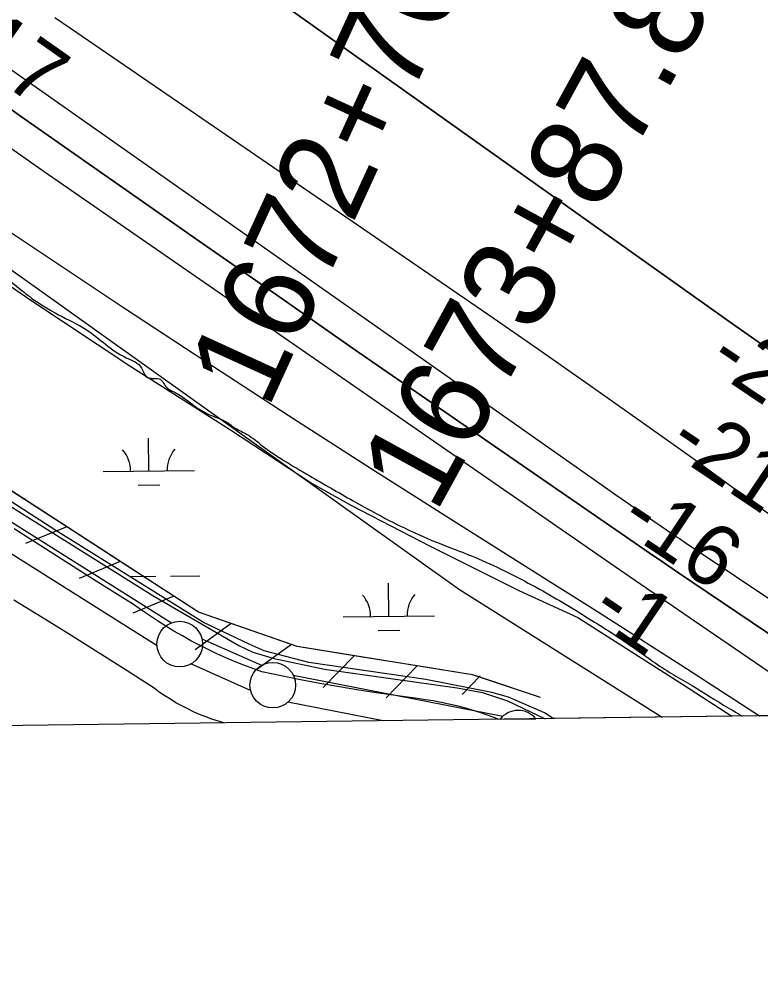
# Model space of a CAD drawing. Extents: x 3734862 to 3772949, y 391520 to 417239.
# Drawn here: x 3760790 to 3761603, y 396853 to 397909 of the extents above; entities that cross this region are included whole.
import ezdxf

# ---------------------------------------------------------------- set-up
doc = ezdxf.new("R2010")
doc.units = 0
for name, color, linetype in [('V-FLOD-BASE', 7, 'Continuous'), ('V-GRID-FRAM', 7, 'Continuous'), ('V-LEVE-TOET', 7, 'Continuous'), ('V-RIVR-EDGE', 7, 'Continuous'), ('V-RIVR-RANG', 7, 'Continuous'), ('V-RRAP-FSHR', 7, 'Continuous'), ('V-SURV-IDEN', 7, 'Continuous'), ('V-SURV-LINE', 7, 'Continuous'), ('V-TOPO-DPTH', 7, 'Continuous'), ('V-TOPO-MINR', 7, 'Continuous'), ('V-TOPO-WATR', 7, 'Continuous'), ('V-WETL-SWMP', 7, 'Continuous')]:
    doc.layers.add(name, color=color, linetype=linetype)

msp = doc.modelspace()

# ---------------------------------------------------------------- linework, layer by layer
at = {"layer": 'V-FLOD-BASE'}
for points in [[(3760932.3, 397256.2), (3760923.6, 397262.2), (3760914.9, 397268.4), (3760871.2, 397295.8), (3760827.6, 397323.3), (3760784.1, 397351)], [(3761315.1, 397142.5), (3761311.1, 397144.1), (3761302.9, 397147.1), (3761294.6, 397150), (3761286.2, 397152.6), (3761277.8, 397155), (3761269.3, 397157.2), (3761260.8, 397159.2), (3761252.2, 397161), (3761243.6, 397162.6), (3761234.9, 397164), (3761226.3, 397165.2), (3761204.8, 397168.1), (3761183.4, 397171.2), (3761162, 397174.5), (3761140.6, 397178.1), (3761119.3, 397181.9), (3761098, 397185.8), (3761076.8, 397190), (3761055.6, 397194.4), (3761045.6, 397198), (3761035.7, 397201.8), (3761025.8, 397205.8), (3761016, 397210), (3761006.3, 397214.3), (3760996.7, 397218.9), (3760987.2, 397223.7), (3760977.8, 397228.6), (3760968.5, 397233.8), (3760959.3, 397239.1), (3760950.2, 397244.6), (3760941.2, 397250.3), (3760932.3, 397256.2)]]:
    msp.add_lwpolyline(points, dxfattribs=at)
at = {"layer": 'V-GRID-FRAM'}
msp.add_lwpolyline([(3738832.3, 415033.8), (3770599.2, 415447.4), (3770843.8, 397266.6), (3739061.1, 396852.8), (3738832.3, 415033.8)], dxfattribs=at)
at = {"layer": 'V-LEVE-TOET'}
for points in [[(3759928.3, 397912.9), (3760072.5, 397820.1), (3760212, 397734.9), (3760300.9, 397673.2), (3760418.6, 397603.9), (3760544.6, 397524.6), (3760663.5, 397449.4), (3760793.1, 397367.7), (3760937.3, 397277.3), (3761030.3, 397223.2), (3761045.6, 397216.2), (3761069.1, 397209.2), (3761124.5, 397197.4), (3761269.8, 397177), (3761297.4, 397171.7), (3761325.1, 397162.9), (3761366.4, 397143.2)], [(3760814.6, 397254.1), (3760783.6, 397273.1)], [(3761014.1, 397138.6), (3761000.9, 397142.6), (3760994.1, 397145.1), (3760987.4, 397147.8), (3760980.8, 397150.7), (3760974.3, 397153.8), (3760967.8, 397157.1), (3760961.5, 397160.7), (3760955.3, 397164.4), (3760949.2, 397168.3), (3760943.2, 397172.4), (3760937.4, 397176.7), (3760906.8, 397196.3), (3760876.2, 397215.8), (3760845.4, 397235), (3760814.6, 397254.1)]]:
    msp.add_lwpolyline(points, dxfattribs=at)
at = {"layer": 'V-RIVR-EDGE'}
for points in [[(3755702.1, 404495.3), (3755757.2, 404470.8), (3755793.3, 404451.2), (3755852.5, 404424.4), (3755881.4, 404415.7), (3755906.2, 404404.4), (3755920.2, 404395.8), (3755948.7, 404379.4), (3755958.2, 404378.9), (3755969, 404378), (3755990.7, 404368.5), (3756022.8, 404350.3), (3756054.8, 404336.6), (3756079.7, 404323), (3756103.6, 404309.4), (3756144.2, 404288), (3756167.7, 404269), (3756188.9, 404253.6), (3756231.4, 404233.1), (3756271.6, 404217.2), (3756299.1, 404203.1), (3756403, 404163.5), (3756460.4, 404140.3), (3756508.7, 404114.9), (3756530.8, 404104), (3756588.2, 404078), (3756639.2, 404052.1), (3756694.3, 404019.5), (3756726.8, 403998.1), (3756735.8, 403989.1), (3756740.3, 403979.6), (3756740.3, 403973.2), (3756740.7, 403967.8), (3756747.5, 403960.5), (3756759.7, 403953.7), (3756786.3, 403941.5), (3756814.3, 403929.2), (3756864.5, 403904.6), (3756889.3, 403896), (3756899.7, 403897.3), (3756908.3, 403901.8), (3756919.2, 403901.3), (3756933.2, 403894.1), (3756945.8, 403892.7), (3756956.2, 403893.1), (3756962.1, 403897.2), (3756970.7, 403896.7), (3756978.4, 403894.4), (3756992.4, 403894.8), (3757002.8, 403897.5), (3757019.1, 403901.5), (3757027.7, 403901.5), (3757034, 403901.1), (3757036.3, 403896.5), (3757036.7, 403891.1), (3757038.5, 403883.4), (3757046.6, 403874.3), (3757060.6, 403866.2), (3757076.4, 403853.9), (3757104.4, 403831.2), (3757122.4, 403816.7), (3757145.5, 403804.5), (3757165.3, 403796.7), (3757181.6, 403787.2), (3757194.2, 403777.7), (3757213.6, 403765.4), (3757229.9, 403756.3), (3757251.6, 403745.9), (3757266.5, 403741.3), (3757283.2, 403734.5), (3757308.9, 403720.9), (3757360.4, 403694.1), (3757393.8, 403670.9), (3757430, 403657.3), (3757461.6, 403645.4), (3757505.4, 403628.1), (3757548.3, 403610.4), (3757591.7, 403587.2), (3757649.5, 403552.3), (3757711.8, 403512.8), (3757753.8, 403493.2), (3757766.9, 403487.8), (3757773.2, 403487.8), (3757785.9, 403494.1), (3757794.5, 403494), (3757803.5, 403489.5), (3757807.1, 403480.9), (3757810.6, 403456), (3757814.2, 403447.9), (3757826.4, 403437), (3757854.4, 403422.9), (3757930.3, 403373.9), (3757975.8, 403342.6), (3758005.2, 403323.5), (3758062.1, 403286.7), (3758092.3, 403263.6), (3758175.8, 403209.6), (3758234.5, 403169.2), (3758283.7, 403133.8), (3758328.8, 403103.4), (3758399.2, 403041.7), (3758421.8, 403023.1), (3758438.1, 403017.7), (3758463.8, 403017.6), (3758491.4, 403026.1), (3758504.5, 403022), (3758513.6, 403014.3), (3758514, 403006.2), (3758499.9, 402997.2), (3758498.1, 402989.9), (3758502.2, 402978.2), (3758510.7, 402969.6), (3758522, 402962.8), (3758545, 402948.7), (3758582.1, 402926.9), (3758650.2, 402878.8), (3758697.6, 402840.7), (3758721.5, 402820.3), (3758740.9, 402809.4), (3758782, 402784.9), (3758831.2, 402755.4), (3758902.1, 402711.8), (3758960.4, 402675.5), (3759018.6, 402634.6), (3759069.6, 402599.7), (3759134.6, 402553.4), (3759185.6, 402508.1), (3759223.5, 402478.1), (3759262.3, 402448.2), (3759321.4, 402402.4), (3759371.5, 402366.1), (3759431.5, 402323.4), (3759463.6, 402300.3), (3759488.9, 402281.7), (3759576.9, 402222.7), (3759627, 402186.8), (3759672.1, 402153.7), (3759778.2, 402087.4), (3759832.8, 402050.7), (3759873, 402019.4), (3759909.5, 401989.4), (3760050.8, 401883.7), (3760100, 401850.2), (3760145.6, 401819.3), (3760185.8, 401788), (3760211.9, 401766.7), (3760254.8, 401734.5), (3760285.5, 401709.1), (3760303.1, 401700.5), (3760325.3, 401691.4), (3760352.8, 401671.4), (3760391.1, 401641), (3760430.4, 401612), (3760461.6, 401590.2), (3760536.9, 401543), (3760583, 401510.8), (3760602.8, 401495.8), (3760629, 401477.2), (3760672.4, 401449.5), (3760711.2, 401426.8), (3760818.6, 401347.8), (3760872.3, 401310.6), (3760925.6, 401271.6), (3760948.6, 401251.7), (3761039.8, 401181.8), (3761107, 401135.5), (3761151.7, 401104.7), (3761172.9, 401093.3), (3761186, 401090.6), (3761199.2, 401092.8), (3761219.5, 401099.1), (3761228.1, 401099.5), (3761233.5, 401095.4), (3761236.7, 401087.7), (3761236.6, 401077.8), (3761228.5, 401063.8), (3761223, 401057.5), (3761223, 401049.3), (3761228.9, 401039.4), (3761242.4, 401026.7), (3761254.1, 401021.7), (3761266.8, 401018.5), (3761292.5, 401001.7), (3761317.3, 400980.4), (3761342.1, 400955.4), (3761463.1, 400853.4), (3761510, 400812.1), (3761550.2, 400777.7), (3761585.3, 400746.8), (3761681.5, 400674.3), (3761756.4, 400618.9), (3761817.8, 400572.2), (3761878.3, 400530.4), (3761996.5, 400436.5), (3762057.4, 400389.8), (3762104.8, 400352.6), (3762156.3, 400313.2), (3762204.5, 400277.3), (3762245.2, 400247.8), (3762291.6, 400210.2), (3762325.9, 400182.1), (3762356.2, 400159.8), (3762404, 400123.6), (3762432.9, 400101.3), (3762455.5, 400091.3), (3762473.5, 400075.9), (3762512.3, 400044.2), (3762551.6, 400012.4), (3762593.6, 399983.8), (3762620.2, 399963.4), (3762661.7, 399937.1), (3762686.6, 399919.8), (3762793.1, 399841.3), (3762834.6, 399812.8), (3762873.4, 399790.1), (3762923.1, 399758.3), (3762957, 399737.4), (3762984, 399721.5), (3763024.2, 399693.4), (3763075.2, 399657.5), (3763115.9, 399633.9), (3763172.8, 399601.2), (3763228.7, 399568.5), (3763285.2, 399533.6), (3763344.3, 399494.1), (3763398.5, 399455.1), (3763444.1, 399421), (3763484.7, 399391.1), (3763603.4, 399303.1), (3763654.8, 399261.8), (3763661.1, 399259.5), (3763667, 399254.5), (3763672, 399245), (3763696.3, 399224.2), (3763722.9, 399200.1), (3763745.5, 399180.2), (3763818.1, 399117.2), (3763841.6, 399099.5), (3763852.4, 399092.2), (3763858.8, 399084.1), (3763875, 399067.3), (3763898, 399046), (3763924.6, 399023.8), (3763949, 399007.9), (3763970.2, 398987.5), (3764004, 398952.6), (3764028.4, 398926.7), (3764056.8, 398899.5), (3764092.9, 398862.4), (3764130.8, 398826.1), (3764147, 398811.6), (3764152.9, 398799.8), (3764162.3, 398783.5), (3764173.6, 398768.6), (3764186.7, 398757.2), (3764206.1, 398746.3), (3764226.9, 398742.2), (3764246.3, 398733.6), (3764269.3, 398717.7), (3764284.2, 398703.2), (3764301.8, 398691.8), (3764323, 398678.2), (3764345.1, 398661), (3764412.4, 398596.6), (3764457, 398559.9), (3764502.6, 398522.7), (3764538.3, 398497.7), (3764566.3, 398486.4), (3764583.9, 398484.5), (3764604.2, 398486.3), (3764616.5, 398486.2), (3764626.4, 398481.7), (3764630.9, 398474.4), (3764636.3, 398461.3), (3764634.9, 398450), (3764631.7, 398441.4), (3764633.1, 398434.7), (3764636.2, 398430.1), (3764643.9, 398425.6), (3764661.1, 398421.5), (3764685.4, 398409.2), (3764715.2, 398382), (3764745.4, 398356.1), (3764793.3, 398328), (3764844.3, 398292.6), (3764885.8, 398258.1), (3764918.8, 398234.5), (3764992.8, 398187.8), (3765058.3, 398144.2), (3765088.1, 398128.3), (3765140.9, 398100.2), (3765168.9, 398079.7), (3765193.7, 398061.6), (3765246.1, 398042), (3765282.2, 398018.4), (3765309.7, 397989.4), (3765340, 397955.4), (3765361.1, 397933.7), (3765382.3, 397911.9), (3765434.7, 397867.9), (3765477.6, 397838.4), (3765508.7, 397823.9), (3765545.3, 397801.2), (3765575.5, 397778), (3765617.5, 397749.9), (3765653.6, 397726.3), (3765681.6, 397710), (3765727.2, 397684.5), (3765762, 397660), (3765771.9, 397659.5), (3765788.2, 397660), (3765793.6, 397658.1), (3765793.6, 397653.6), (3765785.5, 397648.7), (3765785.5, 397645.5), (3765790.9, 397632.8), (3765800.3, 397623.8), (3765814.8, 397612.9), (3765831.9, 397605.6), (3765847.3, 397603.3), (3765858.1, 397598.7), (3765865.8, 397593.3), (3765888.8, 397577), (3765908.7, 397561.5), (3765918.2, 397548.4), (3765919.5, 397542.1), (3765921.3, 397536.2), (3765926.7, 397533.5), (3765933, 397534.4), (3765940.7, 397533.4), (3765944.8, 397530.3), (3765957, 397519.4), (3765987.7, 397499.9), (3766024.7, 397468.1), (3766059.4, 397438.2), (3766085.1, 397413.3), (3766102.7, 397400.1), (3766131.6, 397377.4), (3766172.7, 397350.2), (3766210.6, 397318.9), (3766264.3, 397285.3), (3766306.8, 397260.8), (3766362.7, 397220.8), (3766381.1, 397208.5)], [(3759040.2, 398931), (3759064.4, 398911.6), (3759092.7, 398888), (3759114.1, 398872.6), (3759137.5, 398853.2), (3759176.6, 398819.1), (3759210.1, 398787.5), (3759239.5, 398759.9), (3759277.5, 398727.5), (3759309.7, 398699.9), (3759337.6, 398671.9), (3759369.4, 398643.1), (3759396.1, 398618.8), (3759421.9, 398601.3), (3759451, 398585.1), (3759470, 398572.9), (3759488.5, 398560.3), (3759524.5, 398538.4), (3759537.8, 398529.5), (3759550.3, 398519.7), (3759565.6, 398507.6), (3759581, 398502.3), (3759593.9, 398497), (3759611.3, 398487.7), (3759623, 398478.7), (3759635.9, 398467.4), (3759641.5, 398462.1), (3759650.4, 398457.2), (3759666.6, 398449.9), (3759678.7, 398445.4), (3759700.9, 398434.5), (3759717.9, 398425.1), (3759741.3, 398407.7), (3759774.8, 398379.3), (3759806.3, 398348.9), (3759828.8, 398324.6), (3759851.8, 398297.4), (3759868.4, 398279.2), (3759894.6, 398256.9), (3759920, 398241.4), (3759935.4, 398232.1), (3759976.1, 398198.4), (3760003.6, 398178.6), (3760032.6, 398160.7), (3760062.5, 398142.8), (3760085.1, 398133.5), (3760112.2, 398118.8), (3760130.8, 398103.8), (3760179.6, 398061.3), (3760208.2, 398036.5), (3760224, 398020.3), (3760241.3, 398004.5), (3760263.9, 397987.4), (3760285.7, 397973.2), (3760305.5, 397959.8), (3760330.9, 397942.4), (3760351.5, 397924.6), (3760376.1, 397905.5), (3760414.1, 397881.5), (3760443.5, 397862.5), (3760477.5, 397840.1), (3760515.8, 397813.4), (3760558.2, 397782.9), (3760581.2, 397763.9), (3760591.7, 397757), (3760606.6, 397747.6), (3760619.5, 397738.7), (3760636.9, 397726.9), (3760667.6, 397705), (3760693.8, 397687.2), (3760721.7, 397667.3), (3760754.8, 397642.1), (3760786.7, 397617), (3760803.2, 397604), (3760832.7, 397585.7), (3760863, 397569.5), (3760907, 397538.6), (3760923.5, 397527.3), (3760924.3, 397525.6), (3760925.9, 397522.8), (3760928.3, 397518), (3760932.8, 397516.3), (3760937.2, 397515.9), (3760941.3, 397515.9), (3760946.9, 397512.2), (3760950.6, 397506.6), (3760957.4, 397502.1), (3760969.9, 397494.8), (3760984.1, 397484.2), (3760999.4, 397475.7), (3761016.4, 397468.4), (3761026.5, 397461.5), (3761039.4, 397454.6), (3761058.4, 397440.4), (3761080.2, 397425.8), (3761107.6, 397409.5), (3761155.7, 397381.9), (3761196.1, 397360), (3761222.7, 397347), (3761261.9, 397330.7), (3761289, 397320.1), (3761321.7, 397305.1), (3761356.4, 397287.2), (3761414.5, 397252.7), (3761462.2, 397221.8), (3761502.2, 397194.2), (3761522.3, 397182.5), (3761561.9, 397158.1), (3761582.6, 397146)]]:
    msp.add_spline(points, degree=3, dxfattribs=at)
at = {"layer": 'V-RRAP-FSHR'}
for p, q in [((3760841.7, 397353.3), (3760796.4, 397335)), ((3760900.4, 397315.3), (3760855.2, 397296.9)), ((3760959.2, 397277.3), (3760914, 397258.9)), ((3761021.9, 397247.4), (3760982.4, 397218.7)), ((3761088.1, 397224.5), (3761048.5, 397195.8)), ((3761156.9, 397212.2), (3761122.9, 397177.2)), ((3761226, 397201.1), (3761192, 397166.1)), ((3761295.1, 397190.1), (3761275.3, 397169.6))]:
    msp.add_line(p, q, dxfattribs=at)
for points in [[(3755653.4, 401430.4), (3756537.5, 400803.3), (3758068.9, 399534.7), (3758900.8, 398913.1), (3760489.6, 397842.2), (3761272.5, 397284.7), (3761494.7, 397144.9)], [(3761361.2, 397166.4), (3761286.5, 397191.4), (3761094.5, 397222.3), (3760986.3, 397259.7), (3760712.1, 397437.2), (3760570.9, 397536.9)], [(3760841.7, 397353.3), (3760782.9, 397391.4)], [(3760900.4, 397315.3), (3760841.7, 397353.3)], [(3760959.2, 397277.3), (3760900.4, 397315.3)], [(3761021.9, 397247.4), (3760986.3, 397259.7), (3760959.2, 397277.3)], [(3761088.1, 397224.5), (3761021.9, 397247.4)], [(3761156.9, 397212.2), (3761094.5, 397222.3), (3761088.1, 397224.5)], [(3761226, 397201.1), (3761156.9, 397212.2)], [(3761294.8, 397188.7), (3761286.5, 397191.4), (3761226, 397201.1)], [(3761361.2, 397166.4), (3761294.8, 397188.7)]]:
    msp.add_lwpolyline(points, dxfattribs=at)
at = {"layer": 'V-SURV-LINE'}
msp.add_line((3761316.8, 397142.6), (3761355.9, 397143.1), dxfattribs=at)
for points in [[(3759293.5, 398295.8), (3760956.7, 397248.2)], [(3760940.7, 397222.9), (3759277.5, 398270.4)], [(3760990, 397230.6), (3761055.4, 397201.7)], [(3761043.3, 397174.2), (3760977.8, 397203.1)], [(3761090.1, 397190.7), (3761319.8, 397145.8)], [(3761188.7, 397140.9), (3761084.3, 397161.3)]]:
    msp.add_lwpolyline(points, dxfattribs=at)
for centre in [(3760965.6, 397224.9), (3761067.6, 397179.9)]:
    msp.add_circle(centre, 25, dxfattribs=at)
msp.add_arc((3761336.6, 397127.3), 25, 39.2172, 142.2745, dxfattribs=at)
at = {"layer": 'V-TOPO-DPTH'}
msp.add_line((3761601.4, 397146.3), (3761742.2, 397148.1), dxfattribs=at)
for points in [[(3761742.2, 397148.1), (3761527, 397293.2), (3761511.4, 397303.8), (3761495.9, 397314.3), (3761480.3, 397324.9), (3761464.8, 397335.6), (3761325.9, 397431.2), (3761241, 397489.8), (3761156.2, 397548.5), (3761071.6, 397607.4), (3760986.9, 397666.4), (3760788.3, 397805.2), (3760768.3, 397819.2), (3760748.3, 397833.1), (3760728.2, 397847.1), (3760708.2, 397861.1), (3760071.8, 398303.7)], [(3761742.2, 397148.1), (3761527, 397293.2), (3761511.4, 397303.8), (3761495.9, 397314.3), (3761480.3, 397324.9), (3761464.8, 397335.6), (3761325.9, 397431.2), (3761241, 397489.8), (3761156.2, 397548.5), (3761071.6, 397607.4), (3760986.9, 397666.4), (3760788.3, 397805.2), (3760768.3, 397819.2), (3760748.3, 397833.1), (3760728.2, 397847.1), (3760708.2, 397861.1), (3760071.8, 398303.7)], [(3760014.3, 398221.9), (3760630.4, 397778.1), (3760656.8, 397759.3), (3760683.3, 397740.8), (3760710, 397722.5), (3760736.9, 397704.5), (3760904.1, 397593.7), (3760994.2, 397534.5), (3761084.6, 397475.6), (3761175.4, 397417.4), (3761266.4, 397359.7), (3761382.4, 397286.6), (3761415.7, 397265.7), (3761448.8, 397244.6), (3761481.9, 397223.4), (3761515, 397202.1), (3761601.4, 397146.3)], [(3762176.3, 397153.8), (3761863.3, 397371.2), (3761825.9, 397397.2), (3761788.6, 397423.2), (3761751.4, 397449.3), (3761714.1, 397475.4), (3761705.3, 397481.6), (3761672.5, 397504.7), (3761639.7, 397527.8), (3761607, 397550.9), (3761574.3, 397574.1), (3761084.2, 397922.1)], [(3761084.2, 397922.1), (3761574.3, 397574.1), (3761607, 397550.9), (3761639.7, 397527.8), (3761672.5, 397504.7), (3761705.3, 397481.6), (3761714.1, 397475.4), (3761751.4, 397449.3), (3761788.6, 397423.2), (3761825.9, 397397.2), (3761863.3, 397371.2), (3762176.3, 397153.8)], [(3760828.7, 397911.5), (3760845.7, 397899.8), (3761259.3, 397616.8), (3761309.4, 397582.3), (3761359.5, 397547.6), (3761409.3, 397512.6), (3761459.1, 397477.5), (3761497.8, 397450), (3761528, 397428.5), (3761558.2, 397406.7), (3761588.2, 397384.9), (3761618.1, 397362.9), (3761854.7, 397187.8), (3761906, 397150.2)], [(3760828.7, 397911.5), (3760845.7, 397899.8), (3761259.3, 397616.8), (3761309.4, 397582.3), (3761359.5, 397547.6), (3761409.3, 397512.6), (3761459.1, 397477.5), (3761497.8, 397450), (3761528, 397428.5), (3761558.2, 397406.7), (3761588.2, 397384.9), (3761618.1, 397362.9), (3761854.7, 397187.8), (3761906, 397150.2)]]:
    msp.add_lwpolyline(points, dxfattribs=at)
at = {"layer": 'V-TOPO-MINR'}
for points in [[(3760071.8, 398303.7), (3760708.2, 397861.1), (3760728.2, 397847.1), (3760748.3, 397833.1), (3760768.3, 397819.2), (3760788.3, 397805.2), (3760986.9, 397666.4), (3761071.6, 397607.4), (3761156.2, 397548.5), (3761241, 397489.8), (3761325.9, 397431.2), (3761464.8, 397335.6), (3761480.3, 397324.9), (3761495.9, 397314.3), (3761511.4, 397303.8), (3761527, 397293.2), (3761742.2, 397148.1)], [(3760555.5, 397922.8), (3760598.7, 397893.3), (3760641.9, 397863.7), (3760716.8, 397812.5), (3760722.5, 397808.5), (3760728.3, 397804.6), (3760734, 397800.6), (3760739.7, 397796.6), (3760787.4, 397763.4), (3760816.9, 397742.8), (3760846.5, 397722.3), (3760876.1, 397701.8), (3760905.7, 397681.3), (3761418.3, 397326.9), (3761447.7, 397306.6), (3761477, 397286.4), (3761506.5, 397266.3), (3761535.9, 397246.2), (3761605.1, 397199.1), (3761669.2, 397155.5), (3761681.2, 397147.3)], [(3761084.2, 397922.1), (3761574.3, 397574.1), (3761607, 397550.9), (3761639.7, 397527.8), (3761672.5, 397504.7), (3761705.3, 397481.6), (3761714.1, 397475.4), (3761751.4, 397449.3), (3761788.6, 397423.2), (3761825.9, 397397.2), (3761863.3, 397371.2), (3762176.3, 397153.8)], [(3760690.1, 397919.5), (3760756.9, 397871.5), (3760763, 397867.2), (3760769.1, 397862.8), (3760775.2, 397858.5), (3760781.3, 397854.2), (3761429.7, 397398.4), (3761443.6, 397388.6), (3761457.5, 397378.9), (3761471.5, 397369.2), (3761485.4, 397359.6), (3761508.3, 397343.8), (3761510.9, 397342.1), (3761513.4, 397340.4), (3761516, 397338.6), (3761518.5, 397336.9), (3761632.5, 397260.9), (3761692, 397221.2), (3761751.6, 397181.5), (3761800.9, 397148.9)], [(3760828.7, 397911.5), (3760845.7, 397899.8), (3761259.3, 397616.8), (3761309.4, 397582.3), (3761359.5, 397547.6), (3761409.3, 397512.6), (3761459.1, 397477.5), (3761497.8, 397450), (3761528, 397428.5), (3761558.2, 397406.7), (3761588.2, 397384.9), (3761618.1, 397362.9), (3761854.7, 397187.8), (3761906, 397150.2)]]:
    msp.add_lwpolyline(points, dxfattribs=at)
at = {"layer": 'V-TOPO-WATR'}
msp.add_lwpolyline([(3760014.3, 398221.9), (3760630.4, 397778.1), (3760656.8, 397759.3), (3760683.3, 397740.8), (3760710, 397722.5), (3760736.9, 397704.5), (3760904.1, 397593.7), (3760994.2, 397534.5), (3761084.6, 397475.6), (3761175.4, 397417.4), (3761266.4, 397359.7), (3761382.4, 397286.6), (3761415.7, 397265.7), (3761448.8, 397244.6), (3761481.9, 397223.4), (3761515, 397202.1), (3761601.4, 397146.3)], dxfattribs=at)
at = {"layer": 'V-WETL-SWMP'}
for p, q in [((3760715.2, 397661.2), (3760801.2, 397602.5)), ((3760801.2, 397602.5), (3760911.8, 397529)), ((3760911.8, 397529), (3761021.3, 397459.7)), ((3761021.3, 397459.7), (3761110.8, 397401)), ((3760829.9, 397349.2), (3760665.7, 397454.9)), ((3760931.7, 397414.6), (3760931.4, 397450.6)), ((3760881.7, 397414), (3760981.7, 397415.1)), ((3760919.9, 397399), (3760943.9, 397399.3)), ((3761110.8, 397401), (3761153.8, 397376.9)), ((3761153.8, 397376.9), (3761240.3, 397332.3)), ((3760991.8, 397248.7), (3760829.9, 397349.2)), ((3761240.3, 397332.3), (3761337.4, 397283.6)), ((3760910.9, 397298.9), (3760939.5, 397299.2)), ((3760955.5, 397299.4), (3760987.5, 397299.7)), ((3761194.9, 397255.5), (3761194.5, 397291.5)), ((3761337.4, 397283.6), (3761402.1, 397254.2)), ((3761041.8, 397224.7), (3760991.8, 397248.7)), ((3761144.9, 397254.9), (3761244.9, 397256)), ((3761402.1, 397254.2), (3761518.1, 397180.2)), ((3761183, 397239.9), (3761207, 397240.2)), ((3761058.3, 397217.6), (3761041.8, 397224.7)), ((3761107.1, 397204.7), (3761058.3, 397217.6)), ((3761235.4, 397186), (3761107.1, 397204.7)), ((3761307.7, 397172), (3761235.4, 397186)), ((3761326, 397166.7), (3761307.7, 397172)), ((3761518.1, 397180.2), (3761571, 397145.9)), ((3761365.4, 397149.7), (3761326, 397166.7)), ((3761375.2, 397143.3), (3761365.4, 397149.7)), ((3761571, 397145.9), (3761375.2, 397143.3))]:
    msp.add_line(p, q, dxfattribs=at)
for centre, start, end in [((3760876.5, 397414.5), 359.8334, 41.377), ((3760987, 397415.6), 139.8334, 181.377), ((3761139.6, 397255.4), 359.8334, 41.377), ((3761250.1, 397256.5), 139.8334, 181.377)]:
    msp.add_arc(centre, 35.2, start, end, dxfattribs=at)

# ---------------------------------------------------------------- texts
at = {"layer": 'V-RIVR-RANG'}
for s, rotation, p in [('-17', 324.9498, (3760705.5, 397884.7)), ('-28', 326.1484, (3761541.9, 397529.1)), ('-21', 326.1484, (3761498, 397438.2)), ('-16', 326.1484, (3761444.5, 397353.6)), ('-1', 325.8683, (3761412.9, 397254.6)), ('-1', 325.8683, (3761412.9, 397254.6)), ('-1', 325.8683, (3761412.9, 397254.6))]:
    msp.add_text(s, height=67, rotation=rotation, dxfattribs=at).set_placement(p)
at = {"layer": 'V-SURV-IDEN'}
for s, rotation, p in [('1672+76.3', 65.4192, (3761062, 397480.8)), ('1673+87.8', 61.2817, (3761246, 397366.7))]:
    msp.add_text(s, height=100, rotation=rotation, dxfattribs=at).set_placement(p)

doc.saveas('drawing.dxf')
